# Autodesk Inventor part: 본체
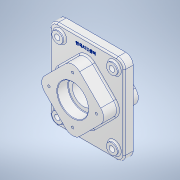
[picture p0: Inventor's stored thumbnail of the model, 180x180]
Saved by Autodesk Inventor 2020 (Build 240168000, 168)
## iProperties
Created: 2021-07
Part Number: 본체
Material: 알루미늄 6061
Document SubType Name: Modeling
Designer: Owner
Density: 2.7 g/cm^3
Appearance: 알루미늄 - 평지
Mass: 2182.04 g
Surface Area: 960.878 cm^2
Volume: 808.161 cm^3
Author: Owner
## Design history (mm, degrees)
sketch "스케치1"
  geometry: L1 (-75, 90)-(75, 90); L2 (75, 90)-(75, -90); L3 (75, -90)-(-75, -90); L4 (-75, -90)-(-75, 90); L5 (-75, 90)-(75, -90); L6 (75, 90)-(-75, -90); 1 further point
  constraints: 12 end point, 2 midpoint, 2 parallel, 1 horizontal, 1 perpendicular
  dimensions: "d0" = 150 distance of L2.end L3.end; "d1" = 180 distance of L1.end L2.end
extrude "돌출1" new body sketch "스케치1" stored distance "d2" = 18; taper "d3" = 0 deg
sketch "스케치2"
  geometry: L1 (75, 90)-(-75, 90) reference; L2 (-75, 90)-(-75, -90) reference; L3 (-75, -90)-(75, -90) reference; L4 (75, -90)-(75, 90) reference; L5 (0, 70.711)-(-70.711, 0); L6 (-70.711, 0)-(0, -70.711); L7 (0, -70.711)-(70.711, 0); L8 (70.711, 0)-(0, 70.711); L9 (0, 70.711)-(0, -70.711); L10 (-70.711, 0)-(70.711, 0); 1 further point
  constraints: 12 end point, 2 midpoint, 2 parallel, 1 perpendicular, 1 vertical
  dimensions: "d4" = 100 distance of L5.start L5.end; "d5" = 100 distance of L6.end L5.end
extrude "돌출2" join sketch "스케치2" distance "d6" = 29; taper "d7" = 0 deg
sketch "스케치3"
  geometry: L1 (75, 90)-(-75, 90) reference; L2 (-75, 90)-(-75, -90) reference; L3 (-75, -90)-(75, -90) reference; L4 (75, -90)-(75, 90) reference; L5 (0, 70.711)-(-70.711, 0); L6 (-70.711, 0)-(0, -70.711); L7 (0, -70.711)-(70.711, 0); L8 (70.711, 0)-(0, 70.711); L9 (0, 70.711)-(0, -70.711); L10 (-70.711, 0)-(70.711, 0); 1 further point
  constraints: 12 end point, 2 midpoint, 2 parallel, 2 perpendicular, 1 vertical
  dimensions: "d8" = 100 distance of L6.end L5.end
extrude "돌출3" join sketch "스케치3" distance "d9" = 23; taper "d10" = 0 deg
sketch "스케치4"
  geometry: C1 r 31 at (0, 0); 1 further point
  constraints: 1 centre point, 1 coincident
  dimensions: "d11" = 62 diameter of C1
hole "구멍1" sketch "스케치4" at (0, 0) diameter "d12" = 45; stored, may be unused: countersink angle "d16" = 90 deg, drill point angle "d18" = 118 deg; dims "d13" = 6, "d14" = 62, "d15" = 22, "d17" = 8
sketch "스케치5" dims "d19" = 96
  geometry: 3 further points
  constraints: 2 vertical alignment, 1 coincident, 2 other
hole "구멍2" sketch "스케치5" at (0, 48) diameter "d20" = 4.917; stored, may be unused: countersink angle "d24" = 90 deg, drill point angle "d26" = 0 deg; dims "d21" = 10, "d22" = 62, "d23" = 22, "d25" = 13
node "작업 평면1"
fillet "모깎기1" dims "d31" = 15
sketch "스케치6"
  geometry: L1 (-75, 75)-(-75, -75) reference; L2 (-60, -90)-(60, -90) reference; L3 (75, -75)-(75, 75) reference; L4 (60, 90)-(-60, 90) reference; L5 (0, 70.711)-(70.711, 0) reference; L6 (70.711, 0)-(0, -70.711) reference; L7 (0, -70.711)-(-70.711, 0) reference; L8 (-70.711, 0)-(0, 70.711) reference; L9 (-55, 70)-(55, 70); C1 r 11 at (-55, 70); C2 r 11 at (55, 70); A1 r 15 centre (-60, 75) between (-60, 90) and (-75, 75) reference; A2 r 15 centre (-60, -75) between (-75, -75) and (-60, -90) reference; A3 r 15 centre (60, -75) between (60, -90) and (75, -75) reference; A4 r 15 centre (60, 75) between (75, 75) and (60, 90) reference; 2 further points
  constraints: 2 centre point, 2 end point, 1 equal radius, 1 horizontal, 1 midpoint, 1 vertical alignment
  dimensions: "d37" = 22 diameter of C1; "d38" = 110 distance of L9.start L9.end; "d39" = 70 distance from line of point (0, 0) L9
extrude "돌출4" join sketch "스케치6" distance "d40" = 5; taper "d41" = 0 deg
sketch "스케치7"
  geometry: C1 r 11 at (0, 0) reference; C2 r 11 at (110, 0) reference; 3 further points
  constraints: 2 coincident
hole "구멍3" sketch "스케치7" at (0, 0), (110, 0) diameter "d42" = 11; stored, may be unused: countersink angle "d46" = 90 deg, drill point angle "d48" = 0 deg; dims "d43" = 11, "d44" = 22, "d45" = 18, "d47" = 29.3
sketch "스케치8"
  geometry: 1 further point
fillet "모깎기2" dims "d49" = 20
fillet "모깎기3" dims "d50" = 3
fillet "모깎기4" dims "d51" = 20
fillet "모깎기5" dims "d52" = 3
fillet "모깎기6" dims "d53" = 3
sketch "스케치9"
  geometry: L1 (60, 90)-(-60, 90) reference; 2 further points
  constraints: 1 other
  dimensions: "d56" = 15 distance from line of L1 point (-2.409, 75)
feature "엠보싱1" sketch "스케치9" dims "d0" = 150, "d1" = 180, "d54" = 0.5, "d55" = 0
chamfer "모따기1" distance "d57" = 1; stored, may be unused: second distance "d58" = 2, angle "d59" = 45 deg
chamfer "모따기2" distance "d60" = 1; stored, may be unused: second distance "d61" = 2, angle "d62" = 45 deg
sketch "스케치10"
  geometry: L1 (-56.569, -14.142)-(-14.142, -56.569) reference; L2 (14.142, -56.569)-(56.569, -14.142) reference; L3 (56.569, 14.142)-(14.142, 56.569) reference; L4 (-14.142, 56.569)-(-56.569, 14.142) reference; C1 r 2.458 at (-48, 0) reference; C2 r 2.458 at (0, -48) reference; C3 r 2.458 at (48, 0) reference; C4 r 2.458 at (0, 48) reference; C5 r 23.5 at (0, 0) reference; C6 r 31 at (0, 0); A1 r 20 centre (-42.426, 0) between (-56.569, 14.142) and (-56.569, -14.142) reference; A2 r 20 centre (0, -42.426) between (-14.142, -56.569) and (14.142, -56.569) reference; A3 r 20 centre (42.426, 0) between (56.569, -14.142) and (56.569, 14.142) reference; A4 r 20 centre (0, 42.426) between (14.142, 56.569) and (-14.142, 56.569) reference; 1 further point
  constraints: 1 centre point, 1 coincident
  dimensions: "d63" = 62 diameter of C6
hole "구멍4" sketch "스케치10" at (0, 0) diameter "d64" = 45; stored, may be unused: countersink angle "d68" = 90 deg, drill point angle "d70" = 0 deg; dims "d65" = 11, "d66" = 62, "d67" = 22, "d69" = 29.3
chamfer "모따기3" distance "d71" = 1; stored, may be unused: second distance "d72" = 2, angle "d73" = 45 deg
fillet "모깎기7" dims "d74" = 3
node "솔리드1"
pattern_circular "원형 패턴1" dims angle "d28" = 360 deg
mirror "미러1"
mirror "미러2"
node "투영된 루프1"
node "투영된 루프2"
node "투영된 루프3"
node "투영된 루프4"
feature "A9D066F2-1C7D-4E18-AEED-F7BC21143FA4" dims "d12" = 45, "d13" = 6, "d14" = 62, "d15" = 22, "d16" = 90 deg, "d17" = 8, "d18" = 118 deg
other parameters: "d30" = -35
